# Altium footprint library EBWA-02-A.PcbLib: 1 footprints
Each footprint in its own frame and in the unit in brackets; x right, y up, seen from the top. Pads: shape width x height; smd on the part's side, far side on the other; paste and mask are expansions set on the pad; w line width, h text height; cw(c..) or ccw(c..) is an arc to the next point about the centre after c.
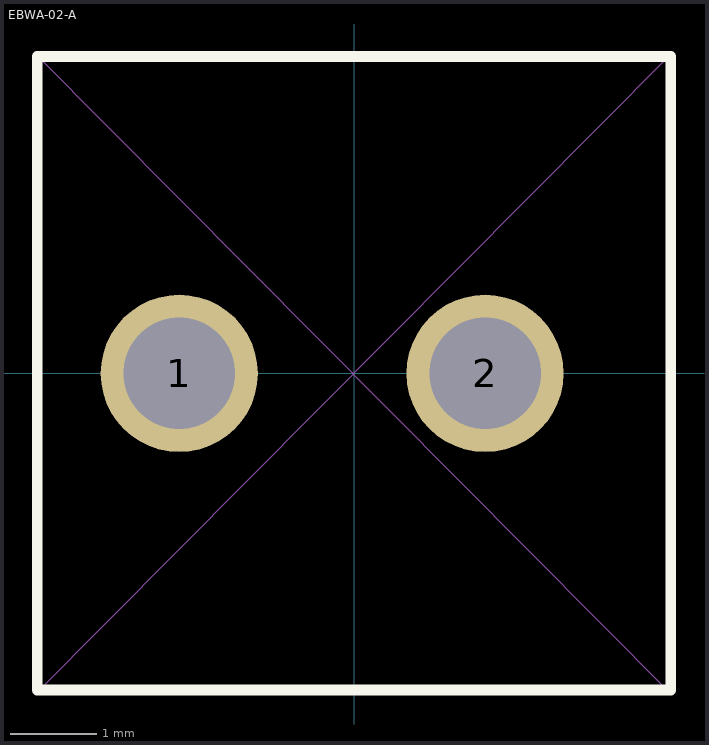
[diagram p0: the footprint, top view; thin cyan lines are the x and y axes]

## EBWA-02-A [mil]
pads (2):
  round 72 hole 51: 1(-80,0) 2(60,0)
Top Overlay:
  lines w5: -145,-145 145,-145 145,145 -145,145 -145,-145
Mechanical 3:
  circle w0.04: c61.73,-2.26 r25.59
  circle w0.04: c-76.06,-2.26 r25.59
  circle w0.02: c61.73,-2.26 r0.01
  circle w0.02: c-0.28,-0.29 r0.01
  circle w0.02: c-76.06,-2.26 r0.01
  lines w0.04: -144.96,-145.96 144.41,145.38 ; -144.96,-145.96 144.41,-145.96 ; -144.96,-145.96 -144.96,145.38 ; -144.96,145.38 144.41,-145.96 ; -144.96,145.38 144.41,145.38 ; 144.41,-145.96 144.41,145.38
